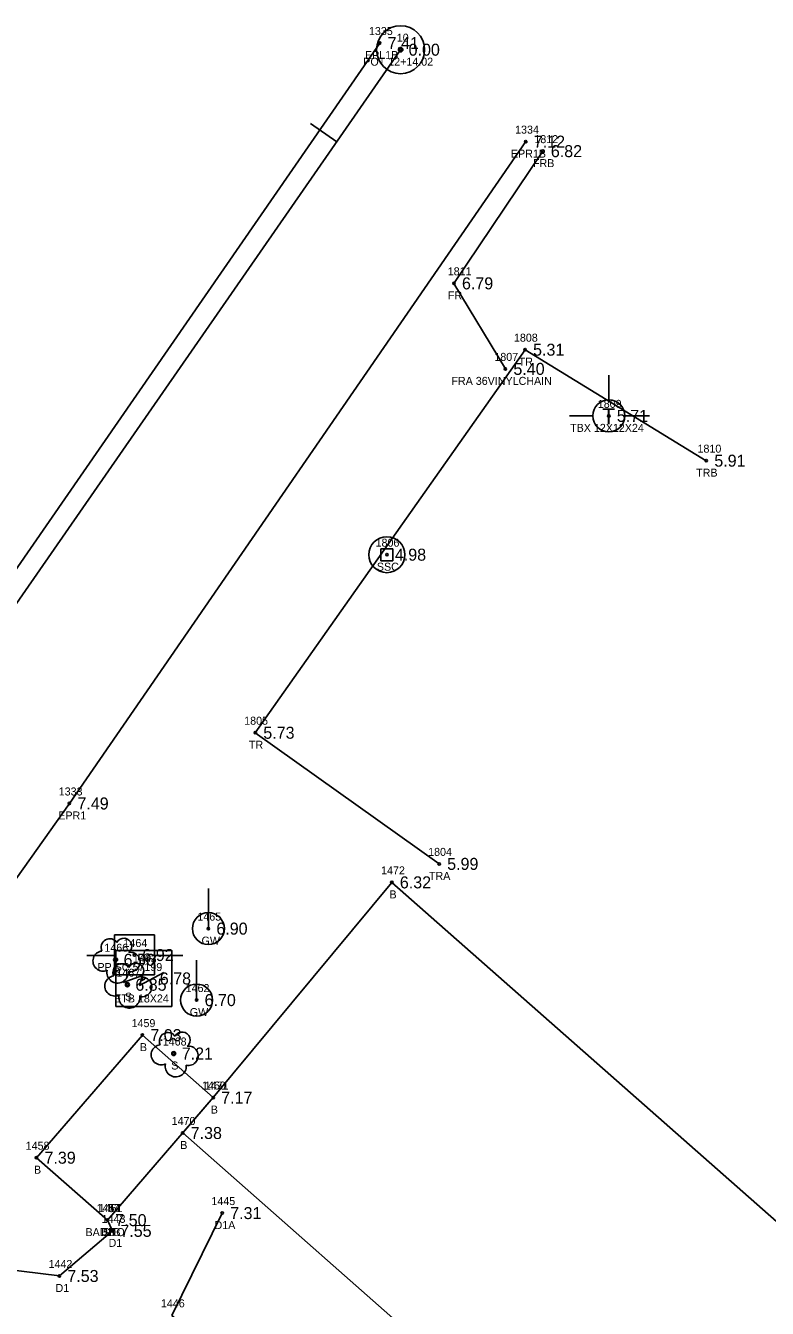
# Model space of a CAD drawing. Extents: x 2608598 to 2610682, y 641451 to 643526.
# Drawn here: x 2609141.9 to 2609234.6, y 643149.1 to 643309.4 of the extents above; entities that cross this region are included whole.
import ezdxf

# ---------------------------------------------------------------- set-up
doc = ezdxf.new("R2010")
doc.units = 0
for name, color, linetype in [('RD_EX_Bldg', 7, 'Continuous'), ('RD_EX_Bldg_txCode', 7, 'Continuous'), ('RD_EX_Driveway', 7, 'Continuous'), ('RD_EX_Driveway_txCode', 7, 'Continuous'), ('RD_EX_Fence_Other', 7, 'Continuous'), ('RD_EX_Fence_Other_txCode', 7, 'Continuous'), ('RD_EX_Road', 7, 'Continuous'), ('RD_EX_Road_txCode', 7, 'Continuous'), ('RD_EX_TX_Bldg_ELEV', 7, 'Continuous'), ('RD_EX_TX_Driveway_ELEV', 7, 'Continuous'), ('RD_EX_TX_Fence_Other_ELEV', 7, 'Continuous'), ('RD_EX_TX_Road_ELEV', 7, 'Continuous'), ('RD_EX_TX_UT_ELEV', 7, 'Continuous'), ('RD_EX_TX_VEG_ELEV', 7, 'Continuous'), ('RD_EX_UT', 7, 'Continuous'), ('RD_EX_UT_txCode', 7, 'Continuous'), ('RD_EX_VEG', 7, 'Continuous'), ('RD_EX_VEG_txCode', 7, 'Continuous'), ('RD_HC_Cl', 7, 'Continuous'), ('RD_HC_Data', 7, 'Continuous'), ('RD_HC_Data_Tic', 7, 'Continuous'), ('RD_HC_Survey_ELEV', 7, 'Continuous'), ('RD_HC_txCode', 7, 'Continuous'), ('RD_SMD_Locator', 7, 'Continuous')]:
    doc.layers.add(name, color=color, linetype=linetype)

msp = doc.modelspace()

# ---------------------------------------------------------------- linework, layer by layer
at = {"layer": 'RD_EX_Bldg'}
for points in [[(2609230.3, 643110.43), (2609161.52, 643171.05), (2609165.34, 643175.48), (2609187.67, 643202.37), (2609256.46, 643141.75), (2609230.3, 643110.43)], [(2609152.1, 643160.16), (2609143.24, 643167.96), (2609156.48, 643183.28), (2609165.34, 643175.48), (2609152.1, 643160.16)]]:
    msp.add_lwpolyline(points, dxfattribs=at)
at = {"layer": 'RD_EX_Driveway'}
for points in [[(2609112.04, 643161.82), (2609127.75, 643155.43), (2609146.1, 643153.18), (2609152.73, 643158.82), (2609152.1, 643160.16)], [(2609166.46, 643161.04), (2609160.17, 643148.26), (2609190.36, 643122.83), (2609213.32, 643102.87), (2609223.77, 643094.8), (2609208.75, 643077.17), (2609183.58, 643050.78)]]:
    msp.add_lwpolyline(points, dxfattribs=at)
at = {"layer": 'RD_EX_Fence_Other'}
msp.add_lwpolyline([(2609201.87, 643266.54), (2609195.44, 643277.23), (2609206.55, 643293.75)], dxfattribs=at)
at = {"layer": 'RD_EX_Road'}
for points in [[(2609058.51, 643155.46), (2609066.22, 643153.94), (2609075.62, 643155.27), (2609079.61, 643157.36), (2609086.3, 643165.29), (2609099.3, 643182.8), (2609111.18, 643198.8), (2609115.92, 643205.68), (2609129.58, 643225.49), (2609186.15, 643307.26)], [(2609096.06, 643119.37), (2609094.92, 643126.79), (2609096.26, 643135.75), (2609098.01, 643141.18), (2609100.57, 643145.92), (2609112.04, 643161.82), (2609127.63, 643184.43), (2609147.36, 643212.23), (2609204.42, 643294.94)]]:
    msp.add_lwpolyline(points, dxfattribs=at)
at = {"layer": 'RD_EX_UT'}
for p, q in [((2609214.8, 643265.74), (2609214.8, 643262.67)), ((2609209.87, 643260.69), (2609212.8, 643260.69)), ((2609216.8, 643260.69), (2609219.87, 643260.69)), ((2609187.8, 643244.07), (2609186.3, 643244.07)), ((2609186.3, 643244.07), (2609186.3, 643242.57)), ((2609187.8, 643242.57), (2609187.8, 643244.07)), ((2609186.3, 643242.57), (2609187.8, 643242.57)), ((2609164.73, 643196.59), (2609164.73, 643201.59)), ((2609157.98, 643195.8), (2609152.98, 643195.8)), ((2609152.98, 643195.8), (2609152.98, 643190.8)), ((2609157.98, 643190.8), (2609157.98, 643195.8)), ((2609149.55, 643193.24), (2609153.02, 643193.24)), ((2609157.91, 643193.24), (2609161.55, 643193.24)), ((2609163.26, 643187.66), (2609163.26, 643192.66)), ((2609152.98, 643190.8), (2609157.98, 643190.8))]:
    msp.add_line(p, q, dxfattribs=at)
msp.add_lwpolyline([(2609153.16, 643186.86), (2609153.16, 643193.86), (2609160.16, 643193.86), (2609160.16, 643186.86)], close=True, dxfattribs=at)
msp.add_lwpolyline([(2609154.06, 643189.85), (2609156.48, 643190.75), (2609156.14, 643189.5), (2609159.18, 643191.1)], dxfattribs=at)
for centre, radius in [((2609214.8, 643260.67), 2), ((2609187.05, 643243.32), 2.25), ((2609164.73, 643196.59), 2), ((2609163.26, 643187.66), 2)]:
    msp.add_circle(centre, radius, dxfattribs=at)
at = {"layer": 'RD_EX_VEG'}
msp.add_lwpolyline([(2609193.59, 643204.68), (2609170.6, 643221.07), (2609204.33, 643268.94), (2609226.99, 643255.07)], dxfattribs=at)
for centre in [(2609153.13, 643192.7), (2609154.6, 643189.58), (2609160.4, 643180.98)]:
    msp.add_circle(centre, 0.25, dxfattribs=at)
for centre, radius, start, end in [((2609152.41, 643194.25), 1.08, 34.9763, 204.756), ((2609154.17, 643194.4), 0.995, 308.7626, 152.0467), ((2609151.56, 643192.54), 1.26, 96.4518, 294.734), ((2609154.97, 643192.42), 1.22, 256.5667, 98.1046), ((2609153.88, 643191.13), 1.08, 34.9763, 204.756), ((2609155.65, 643191.28), 0.995, 308.7626, 152.0467), ((2609153.04, 643189.42), 1.26, 96.4518, 294.734), ((2609153.37, 643191.1), 1.32, 166.8827, 5.7589), ((2609156.44, 643189.3), 1.22, 256.5667, 98.1046), ((2609154.85, 643187.98), 1.32, 166.8827, 5.7589), ((2609159.68, 643182.52), 1.08, 34.9763, 204.756), ((2609161.45, 643182.68), 0.995, 308.7626, 152.0467), ((2609158.84, 643180.82), 1.26, 96.4518, 294.734), ((2609162.24, 643180.7), 1.22, 256.5667, 98.1046), ((2609160.65, 643179.38), 1.32, 166.8827, 5.7589)]:
    msp.add_arc(centre, radius, start, end, dxfattribs=at)
at = {"layer": 'RD_HC_Cl'}
msp.add_line((2609066.72, 643130.62), (2609188.77, 643306.43), dxfattribs=at)
at = {"layer": 'RD_HC_Data'}
for radius in [3, 0.282]:
    msp.add_circle((2609188.77, 643306.43), radius, dxfattribs=at)
at = {"layer": 'RD_HC_Data_Tic'}
msp.add_line((2609180.78, 643294.91), (2609177.49, 643297.2), dxfattribs=at)
at = {"layer": 'RD_SMD_Locator'}
for centre in [(2609186.15, 643307.26), (2609188.77, 643306.43), (2609204.42, 643294.94), (2609206.55, 643293.75), (2609195.44, 643277.23), (2609204.33, 643268.94), (2609201.87, 643266.54), (2609214.8, 643260.67), (2609226.99, 643255.07), (2609187.05, 643243.32), (2609170.6, 643221.07), (2609147.36, 643212.23), (2609193.59, 643204.68), (2609187.67, 643202.37), (2609164.73, 643196.59), (2609153.13, 643192.7), (2609155.49, 643193.29), (2609156.66, 643190.36), (2609154.6, 643189.58), (2609163.26, 643187.66), (2609156.48, 643183.28), (2609160.4, 643180.98), (2609165.34, 643175.48), (2609165.34, 643175.48), (2609161.52, 643171.05), (2609143.24, 643167.96), (2609152.1, 643160.16), (2609152.1, 643160.16), (2609152.1, 643160.16), (2609166.46, 643161.04), (2609152.73, 643158.82), (2609146.1, 643153.18)]:
    msp.add_circle(centre, 0.15, dxfattribs=at)

# ---------------------------------------------------------------- texts
at = {"layer": 'RD_EX_Bldg_txCode'}
for s, p in [('1472', (2609186.33, 643203.37)), ('B', (2609187.37, 643200.37)), ('1459', (2609155.13, 643184.28)), ('B', (2609156.17, 643181.28)), ('1460', (2609163.93, 643176.48)), ('1471', (2609164.28, 643176.48)), ('B', (2609165.03, 643173.48)), ('B', (2609165.03, 643173.48)), ('1470', (2609160.14, 643172.05)), ('1458', (2609141.89, 643168.96)), ('B', (2609161.22, 643169.05)), ('B', (2609142.93, 643165.96)), ('1457', (2609150.75, 643161.16)), ('1461', (2609151.01, 643161.16)), ('BA STO', (2609149.37, 643158.16)), ('BB', (2609151.32, 643158.16))]:
    msp.add_text(s, height=1, dxfattribs=at).set_placement(p)
at = {"layer": 'RD_EX_Driveway_txCode'}
for s, p in [('1445', (2609165.11, 643162.04)), ('1444', (2609150.75, 643161.16)), ('1443', (2609151.39, 643159.82)), ('D1A', (2609165.5, 643159.04)), ('D1B', (2609151.15, 643158.16)), ('D1', (2609152.26, 643156.82)), ('1442', (2609144.75, 643154.18)), ('D1', (2609145.62, 643151.18)), ('1446', (2609158.8, 643149.26))]:
    msp.add_text(s, height=1, dxfattribs=at).set_placement(p)
at = {"layer": 'RD_EX_Fence_Other_txCode'}
for s, p in [('1812', (2609205.49, 643294.75)), ('FRB', (2609205.32, 643291.75)), ('1811', (2609194.66, 643278.23)), ('FR', (2609194.68, 643275.23)), ('1807', (2609200.49, 643267.54)), ('FRA 36VINYLCHAIN', (2609195.12, 643264.54))]:
    msp.add_text(s, height=1, dxfattribs=at).set_placement(p)
at = {"layer": 'RD_EX_Road_txCode'}
for s, p in [('1335', (2609184.81, 643308.26)), ('EPL1B', (2609184.31, 643305.26)), ('1334', (2609203.08, 643295.94)), ('EPR1B', (2609202.56, 643292.94)), ('1333', (2609146.02, 643213.23)), ('EPR1', (2609145.97, 643210.23))]:
    msp.add_text(s, height=1, dxfattribs=at).set_placement(p)
at = {"layer": 'RD_EX_TX_Bldg_ELEV'}
for s, p in [('6.32', (2609188.67, 643201.62)), ('7.03', (2609157.48, 643182.53)), ('7.17', (2609166.34, 643174.73)), ('7.17', (2609166.34, 643174.73)), ('7.38', (2609162.52, 643170.3)), ('7.39', (2609144.24, 643167.21)), ('7.50', (2609153.1, 643159.41)), ('7.50', (2609153.1, 643159.41))]:
    msp.add_text(s, height=1.5, dxfattribs=at).set_placement(p)
at = {"layer": 'RD_EX_TX_Driveway_ELEV'}
for s, p in [('7.31', (2609167.46, 643160.29)), ('7.50', (2609153.1, 643159.41)), ('7.55', (2609153.73, 643158.07)), ('7.53', (2609147.1, 643152.43))]:
    msp.add_text(s, height=1.5, dxfattribs=at).set_placement(p)
at = {"layer": 'RD_EX_TX_Fence_Other_ELEV'}
for s, p in [('6.82', (2609207.55, 643293)), ('6.79', (2609196.44, 643276.48)), ('5.40', (2609202.87, 643265.79))]:
    msp.add_text(s, height=1.5, dxfattribs=at).set_placement(p)
at = {"layer": 'RD_EX_TX_Road_ELEV'}
for s, p in [('7.41', (2609187.15, 643306.51)), ('7.12', (2609205.42, 643294.19)), ('7.49', (2609148.36, 643211.48))]:
    msp.add_text(s, height=1.5, dxfattribs=at).set_placement(p)
at = {"layer": 'RD_EX_TX_UT_ELEV'}
for s, p in [('5.71', (2609215.8, 643259.92)), ('4.98', (2609188.05, 643242.57)), ('6.90', (2609165.73, 643195.84)), ('6.78', (2609158.66, 643189.61)), ('6.70', (2609164.26, 643186.91))]:
    msp.add_text(s, height=1.5, dxfattribs=at).set_placement(p)
at = {"layer": 'RD_EX_TX_VEG_ELEV'}
for s, p in [('5.31', (2609205.33, 643268.19)), ('5.91', (2609227.99, 643254.32)), ('5.73', (2609171.6, 643220.32)), ('5.99', (2609194.59, 643203.93)), ('6.56', (2609154.13, 643191.95)), ('6.85', (2609155.6, 643188.83)), ('7.21', (2609161.4, 643180.23))]:
    msp.add_text(s, height=1.5, dxfattribs=at).set_placement(p)
at = {"layer": 'RD_EX_UT'}
msp.add_text('T', height=2, dxfattribs=at).set_placement((2609213.95, 643259.63))
at = {"layer": 'RD_EX_UT_txCode'}
for s, p in [('1809', (2609213.42, 643261.67)), ('TBX 12X12X24', (2609209.96, 643258.67)), ('1806', (2609185.64, 643244.32)), ('SSC', (2609185.8, 643241.32)), ('1465', (2609163.36, 643197.59)), ('1464', (2609154.12, 643194.29)), ('GW', (2609163.88, 643194.59)), ('PP SC 57199', (2609150.86, 643191.29)), ('1463', (2609155.29, 643192.36)), ('1462', (2609161.89, 643188.66)), ('ETB 18X24', (2609152.95, 643187.36)), ('GW', (2609162.41, 643185.66))]:
    msp.add_text(s, height=1, dxfattribs=at).set_placement(p)
at = {"layer": 'RD_EX_VEG_txCode'}
for s, p in [('1808', (2609202.94, 643269.94)), ('TR', (2609203.53, 643266.94)), ('1810', (2609225.89, 643256.07)), ('TRB', (2609225.72, 643253.07)), ('1805', (2609169.21, 643222.07)), ('TR', (2609169.8, 643219.07)), ('1804', (2609192.21, 643205.68)), ('TRA', (2609192.31, 643202.68)), ('1466', (2609151.73, 643193.7)), ('S', (2609152.82, 643190.7)), ('1467', (2609153.23, 643190.58)), ('S', (2609154.3, 643187.58)), ('1468', (2609159.03, 643181.98)), ('S', (2609160.09, 643178.98))]:
    msp.add_text(s, height=1, dxfattribs=at).set_placement(p)
at = {"layer": 'RD_HC_Survey_ELEV'}
for s, p in [('0.00', (2609189.77, 643305.68)), ('6.92', (2609156.49, 643192.54))]:
    msp.add_text(s, height=1.5, dxfattribs=at).set_placement(p)
at = {"layer": 'RD_HC_txCode'}
for s, p in [('10', (2609188.29, 643307.43)), ('POT 12+14.02', (2609184.1, 643304.43))]:
    msp.add_text(s, height=1, dxfattribs=at).set_placement(p)

doc.saveas('drawing.dxf')
